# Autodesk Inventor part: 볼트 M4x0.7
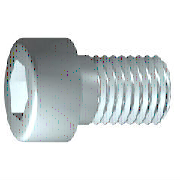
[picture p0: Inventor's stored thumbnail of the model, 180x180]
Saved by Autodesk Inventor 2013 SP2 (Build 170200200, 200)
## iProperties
IsCustomPart: 1
Created: 2015-10
Part Number: 볼트 M4x0.7
Material: 스테인리스강
Description: 6각머리 태핑 나사
Document SubType Name: Modeling
Standard: KS B 1003
Designer: mdu
Standards Organization: KS
Language: ko-KR
Size Designation: M 4 x 16
Categories: <MemberInstance><Categories><Category DisplayName="조임쇠" InternalName="e4da775c-781d-43d5-af7c-5136215cf5a6" Mnemonic="FSTN"><Category DisplayName="볼트" InternalN
Density: 8.08 g/cm^3
Mass: 2.70334 g
Surface Area: 3.81118 cm^2
Volume: 0.334572 cm^3
Author: mdu
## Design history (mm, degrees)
sketch "스케치1"
  geometry: L1 (-1, 0)-(16, 0); L2 (16, 0)-(16, 2); L3 (16, 2)-(1.75, 2); L4 (1.75, 2)-(1.32, 2); L5 (1.32, 2)-(0, 2); L6 (0, 2)-(0, 3.5); L7 (0, 3.5)-(-4, 3.5); L8 (-4, 3.5)-(-4, 1.732); L9 (-4, 1.732)-(-2, 1.732); L10 (-2, 1.732)-(-1, 0); L11 (-8, 0)-(20, 0) reference; L12 (0, -0.7)-(0, 4.2) reference; L13 (1.75, 2)-(0, 2)
  constraints: 22 end point, 6 parallel, 2 collinear, 2 perpendicular, 1 horizontal, 1 point on line
  dimensions: "d1" = 14.25 distance from line of L3.end L2 (= GEL); "d2" = 0.42952 distance of L4.end L3.end (computed from GAL); "d3" = 4 distance between parallel lines of L8 L6 (= KOH); "d4" = 2 distance of L8.end L9.end (= INTI); "d5" = 60 deg angle of L10 L1; "d6" = 4 diameter of L3 L1 (= GD); "d7" = 4 diameter of L5 L1 (= BDM); "d8" = 3.4641 diameter of L9 L1 (= 1.1547 x SW); "d9" = 7 diameter of L7 L1 (= KOD); "d26" = 16 distance between parallel lines of L12 L2 (= NLG)
revolve "본체" sketch "스케치1" stored, may be unused: angle "d10" = 90 deg
sketch "스케치2"
  geometry: L1 (0, -4.9)-(0, 4.9) reference; L2 (-4.9, 0)-(4.9, 0) reference; L3 (1.732, 0)-(0.866, -1.5); L4 (0.866, -1.5)-(-0.866, -1.5); L5 (-0.866, -1.5)-(-1.732, 0); L6 (-1.732, 0)-(-0.866, 1.5); L7 (-0.866, 1.5)-(0.866, 1.5); L8 (0.866, 1.5)-(1.732, 0); 2 further points
  constraints: 12 end point, 1 coincident, 1 horizontal alignment, 1 point on line, 12 other
extrude "슬롯" join sketch "스케치2" stored distance "d11" = 10; taper "d12" = 0 deg
workplane "Work Plane1"
fillet "Fillet2" dims "d30" = 0.1 (= R)
body "Solid1"
fillet "모깎기1" dims "d17" = 0.4 (= RR)
feature "스레드" dims "d13" = 14.25 (= GEL), "d14" = 0
chamfer "모따기1" distance "d15" = 0.42941 (= -0.5 x SPD + 0.5 x GD); stored, may be unused: second distance "d16" = 0.42941 (= GUL), angle "d27" = 45 deg
other parameters: "GD" = 4 (= NND) [user parameter; used in 2 equation terms], "NLG" = 16 [user parameter; used in 1 equation term], "GEL" = 14.25 [user parameter; used in 2 equation terms], "KOD" = 7 [user parameter; used in 1 equation term], "KOH" = 4 [user parameter; used in 1 equation term], "INTI" = 2 [user parameter; used in 1 equation term], "GAL" = 0.42941 (= 0.61345 x PTC) [user parameter; used in 1 equation term], "GUL" = 0.42941 (= 0.61345 x PTC) [user parameter; used in 1 equation term], "BDM" = 4 (= NND) [user parameter; used in 1 equation term], "SW" = 3 [user parameter; used in 2 equation terms], "RR" = 0.4 [user parameter; used in 1 equation term], "SPD" = 3.14117 (= NND - 1.2269 x PTC) [user parameter; used in 1 equation term], "d19" = 0, "d28" = 0, "d29" = 0, "R" = 0.1 [user parameter; used in 1 equation term], "PHH" = 0.2 [user parameter], "GD1" = 3.14117 (= THREADDIA - 1.2269 x PTC) [user parameter], "THREADDIA" = 4 [user parameter; used in 1 equation term], "FAWI" = 45 deg [user parameter], "TPU" = 14.28571 (computed from PTC) [user parameter], "PTC" = 0.7 [user parameter; used in 5 equation terms], "NND" = 4 [user parameter; used in 3 equation terms], "TOA" = 30 deg [user parameter], "E0" = 3.465 (= 1.155 x SW) [user parameter]
